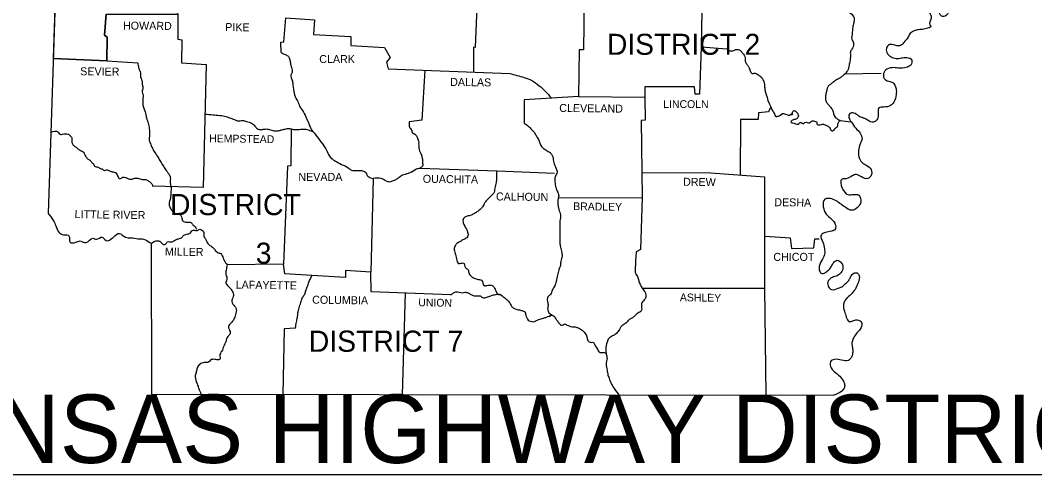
# Model space of a CAD drawing. Extents: x -13171 to 18763, y -8840 to 11152.
# Drawn here: x 10714 to 16044, y 4654 to 7050 of the extents above; entities that cross this region are included whole.
import ezdxf

# ---------------------------------------------------------------- set-up
doc = ezdxf.new("R2010")
doc.units = 0
for name, color, linetype in [('Level 1', 7, 'Continuous'), ('Level 2', 7, 'Continuous'), ('Level 3', 7, 'Continuous'), ('Level 48', 7, 'Continuous')]:
    doc.layers.add(name, color=color, linetype=linetype)

msp = doc.modelspace()

# ---------------------------------------------------------------- linework, layer by layer
at = {"layer": 'Level 1'}
for p, q in [((15042.6, 6768.2), (15238.2, 6771.2)), ((9238.8, 4659.5), (17153.7, 4659.5))]:
    msp.add_line(p, q, dxfattribs=at)
for points in [[(10745.4, 10313), (10947.9, 8686.9), (10859.9, 6032.5)], [(13678.7, 7289.7), (13672.8, 6894.4), (13650.3, 6893.5), (13647.3, 6647.9)], [(14299.1, 7294.1), (14291.1, 6910.1), (14427.1, 6899.3)], [(13115.1, 7162.5), (13103.4, 6906.2), (13094.5, 6909.1), (13095.5, 6776)], [(11165.1, 7082.3), (11156.3, 6970.8), (11170, 6961), (11169, 6835.7), (10887, 6848.1)], [(11541.8, 7081.3), (11541.8, 6951.2), (11563.3, 6947.3), (11561.4, 6825.9), (11690.5, 6816.2), (11674.9, 6169.4), (11408.8, 6176.3)], [(12084.8, 6880.7), (12082.9, 6934.5), (12098.5, 6935.5), (12108.3, 7061.7), (12259, 7052), (12255.1, 6974.7), (12449.8, 6963.9), (12450.8, 6916.9), (12626.9, 6906.2), (12657.2, 6853.3), (12638.6, 6829.9), (12647.4, 6793.7), (13285.3, 6770.2)], [(14291.1, 6910.1), (14282.3, 6661.6), (14259.8, 6661.6), (14255.9, 6699.7), (13995.7, 6699.7), (13995.7, 6644.9)], [(11169, 6835.7), (11331.5, 6825.9)], [(12839.9, 6786.6), (12824.5, 6523.6), (12757, 6515.8)], [(13506.5, 6639.1), (13361.7, 6630.3), (13360.7, 6508)], [(13647.3, 6647.9), (13504.5, 6639.1)], [(13647.3, 6647.9), (13995.7, 6645.9)], [(13995.7, 6645.9), (13996.6, 6523.6), (13976.1, 6522.6), (13982, 6116.6)], [(14657.1, 6594.1), (14645.3, 6567.6), (14593.5, 6562.8), (14590.5, 6527.5), (14497.6, 6527.5), (14496.6, 6235)], [(14766.6, 6551), (14769.6, 6553.9), (14772.5, 6556.9), (14772.5, 6556.9)], [(12136.7, 6478.6), (12134.7, 6283.9), (12117.1, 6282), (12097.5, 5766.3)], [(12814.7, 6272.2), (13219.8, 6257.5), (13520.2, 6245.8)], [(13979, 6249.7), (14342, 6246.7), (14623.8, 6225.2)], [(12568.2, 6217.4), (12555.4, 5724.3), (12423.4, 5733.1), (12422.4, 5696.9), (12246.3, 5707.6)], [(14623.8, 6225.2), (14623.8, 5640.1), (14631.6, 5077.5)], [(13539.7, 6115.6), (13982, 6116.6)], [(13982, 6116.6), (13972.2, 5844.6), (13950.7, 5830.9)], [(11400.9, 5874.9), (11402.9, 5083.4), (14988.7, 5077.5)], [(14628.7, 5913.1), (14759.8, 5905.3), (14765.7, 5848.5), (14884.1, 5852.4), (14888.9, 5900.4), (14911.4, 5900.4)], [(12246.3, 5707.6), (12104.4, 5715.5), (12097.5, 5766.3), (11801.1, 5763.4)], [(12975.2, 5604.9), (12557.4, 5620.5), (12555.3, 5724.3)], [(12735.5, 5613.9), (12720, 5081.2)], [(13981.6, 5641.1), (14623.8, 5641.1)], [(12160.2, 5430.7), (12099.5, 5426.8), (12092.7, 5082.4)]]:
    msp.add_lwpolyline(points, dxfattribs=at)
for points in [[(15812.6, 7720.2), (15790.1, 7691.8), (15756.8, 7709.4), (15756.8, 7732.9), (15761.7, 7757.4), (15749.9, 7773), (15729.4, 7766.2), (15729.4, 7735.9), (15727.4, 7706.5), (15721.6, 7664.4), (15735.3, 7651.7), (15766.6, 7647.8), (15789.1, 7641.9), (15802.8, 7619.4), (15801.8, 7592), (15791, 7565.6), (15775.4, 7544.1), (15750.9, 7536.3), (15731.4, 7549), (15723.5, 7574.4), (15714.7, 7596.9), (15698.1, 7613.6), (15680.5, 7595), (15676.6, 7560.7), (15677.5, 7531.4), (15677.5, 7491.3), (15703, 7464.8), (15718.6, 7434.5), (15713.7, 7407.1), (15695.2, 7374.8), (15687.3, 7346.5), (15679.5, 7308.3), (15680.5, 7266.2), (15673.6, 7225.1), (15659.9, 7197.7), (15634.5, 7175.2), (15617.9, 7160.6), (15604.2, 7145.9), (15597.3, 7116.5), (15592.4, 7096), (15573.8, 7071.5), (15559.2, 7069.6), (15547.4, 7079.4), (15543.5, 7096), (15543.5, 7112.6), (15535.7, 7129.3), (15511.2, 7136.1), (15491.6, 7135.1), (15482.8, 7121.4), (15495.6, 7083.3), (15500.4, 7058.8), (15493.6, 7025.5), (15497.5, 7021.6), (15462.3, 7003), (15433.9, 7000.1), (15410.4, 6993.3), (15387.9, 6978.6), (15377.2, 6957.1), (15361.5, 6939.4), (15347.8, 6922.8), (15329.2, 6915), (15308.7, 6918.9), (15281.3, 6921.8), (15265.6, 6902.3), (15270.5, 6873.9), (15289.1, 6857.3), (15316.5, 6849.4), (15344.9, 6851.4), (15372.3, 6854.3), (15397.7, 6840.6), (15392.8, 6814.2), (15368.4, 6801.5), (15332.2, 6797.6), (15302.8, 6800.5), (15267.6, 6792.7), (15250, 6770.2), (15259.8, 6735.9), (15297.9, 6722.2), (15315.5, 6689.9), (15316.5, 6659.6), (15303.8, 6619.5), (15286.2, 6600.9), (15251.9, 6593.1), (15225.5, 6588.2), (15221.6, 6543.2), (15209.9, 6520.7), (15189.3, 6513.8), (15160, 6528.5), (15142.4, 6535.4), (15120.8, 6545.1), (15093.4, 6561.8), (15072.9, 6558.8), (15078.8, 6515.8), (15080.7, 6513.8), (15104.2, 6481.5), (15127.7, 6456.1), (15138.4, 6425.8)], [(14798.9, 7405.2), (14801.9, 7365), (14825.3, 7359.2), (14835.1, 7348.4), (14840, 7325.9), (14856.7, 7316.1), (14879.2, 7302.4), (14892.9, 7292.6), (14902.6, 7277), (14908.5, 7251.6), (14924.2, 7234.9), (14945.7, 7227.1), (14961.3, 7208.5), (14971.1, 7182.1), (14986.8, 7170.3), (15002.4, 7149.8), (15010.3, 7141), (15024, 7117.5), (15037.7, 7105.8), (15047.4, 7098.9), (15063.1, 7094), (15082.7, 7081.3), (15095.4, 7061.7), (15095.4, 7047.1), (15090.5, 7024.6), (15086.6, 7001.1), (15084.6, 6974.7), (15082.7, 6951.2), (15091.5, 6931.6), (15086.6, 6902.3), (15076.8, 6886.6), (15075.8, 6865.1), (15072.9, 6832.8), (15069, 6814.2), (15060.2, 6783.9), (15047.4, 6768.2)], [(12084.8, 6880.7), (12100.5, 6871), (12119.1, 6862.1), (12128.9, 6847.5), (12132.8, 6825), (12139.6, 6800.5), (12141.6, 6775.1), (12135.7, 6761.4), (12143.5, 6730.1), (12146.5, 6708.5), (12149.4, 6683.1), (12157.2, 6648.9), (12170, 6625.4), (12181.7, 6597), (12201.3, 6566.7), (12217.9, 6533.4), (12225.7, 6515.8), (12240.4, 6479.6), (12259, 6455.1), (12288.3, 6418), (12314.8, 6379.8), (12329.4, 6351.4), (12351.9, 6320.1), (12377.4, 6304.5), (12409.7, 6287.8), (12430.2, 6278), (12453.7, 6261.4), (12484, 6259.4), (12506.5, 6259.4), (12527.1, 6250.6), (12536.9, 6233), (12554.5, 6221.3), (12568.2, 6217.4)], [(14427.1, 6899.3), (14441.8, 6889.5), (14462.4, 6890.5), (14476.1, 6896.4), (14486.8, 6895.4), (14501.5, 6886.6), (14511.3, 6874.9), (14518.1, 6866.1), (14523, 6852.4), (14523, 6839.6), (14527.9, 6822), (14533.8, 6815.2), (14541.6, 6802.5), (14546.5, 6790.7), (14549.4, 6782.9), (14560.2, 6770.2), (14570, 6771.2), (14578.8, 6770.2), (14590.5, 6763.3), (14608.1, 6749.6), (14611.1, 6745.7), (14622.8, 6720.3), (14624.8, 6704.6), (14626.7, 6684.1), (14630.6, 6664.5), (14638.5, 6643), (14642.4, 6628.3), (14651.2, 6607.8), (14657.1, 6594.1), (14664.9, 6576.5), (14676.6, 6556.9), (14681.5, 6545.1), (14698.2, 6546.1), (14709.9, 6551), (14718.7, 6558.8), (14729.5, 6557.9), (14741.2, 6553.9), (14756.9, 6551), (14766.6, 6556.9), (14771.5, 6560.8), (14772.5, 6569.6), (14781.3, 6574.5), (14791.1, 6567.6), (14801.9, 6552), (14801.9, 6542.2), (14798, 6536.3), (14785.2, 6528.5), (14767.6, 6522.6), (14762.7, 6515.8), (14779.4, 6508), (14805.8, 6506), (14812.6, 6511.9), (14830.2, 6507), (14837.1, 6511.9), (14860.6, 6510.9), (14871.3, 6518.7), (14892.9, 6517.7), (14899.7, 6512.9), (14899.7, 6504.1), (14917.3, 6500.1), (14930, 6503.1), (14946.7, 6498.2), (14961.3, 6490.4), (14969.2, 6479.6), (14979, 6467.8), (14987.8, 6470.8), (14994.6, 6479.6), (15009.3, 6495.2), (15009.3, 6505), (15013.2, 6511.9), (15019.6, 6524.7)], [(11331.5, 6825.9), (11336.3, 6796.6), (11345.2, 6771.2), (11346.1, 6751.6), (11354.9, 6722.2), (11354.9, 6711.5), (11357.9, 6689.9), (11354, 6678.2), (11358.9, 6654.7), (11357.9, 6637.1), (11357.9, 6622.4), (11358.9, 6598), (11366.7, 6576.5), (11374.5, 6544.2), (11379.4, 6527.5), (11387.2, 6502.1), (11392.1, 6470.8), (11393.1, 6447.3), (11391.1, 6425.8), (11397, 6401.3), (11407.8, 6376.9), (11421.5, 6353.4), (11438.1, 6327), (11449.8, 6306.4), (11464.5, 6283.9), (11476.3, 6265.3), (11493.9, 6241.8), (11501.7, 6222.3), (11501.7, 6194.9), (11505.6, 6169.4), (11504.6, 6141.1), (11502.7, 6115.6), (11495.8, 6080.4), (11500.7, 6063.8), (11519.3, 6039.3), (11531.1, 6032.5), (11551.6, 6028.5), (11561.4, 6014.8), (11567.3, 5994.3), (11587.8, 5987.5), (11610.3, 5985.5), (11621.1, 5973.8), (11635.7, 5958.1), (11640.6, 5950.3)], [(13285.3, 6770.2), (13361.7, 6748.7), (13400.8, 6734), (13439.9, 6705.6), (13472.2, 6677.2), (13504.5, 6639.1)], [(15047.4, 6768.2), (15040.9, 6762.1), (15034.2, 6756.3), (15027.3, 6750.8), (15020, 6745.7), (15015.7, 6743.2), (15011.2, 6740.9), (15006.7, 6738.6), (15002.4, 6735.9), (14983.8, 6722.2), (14972.6, 6713.9), (14967, 6709.8), (14961.3, 6705.6), (14956.6, 6700), (14953.9, 6692.9), (14952.2, 6685), (14951.4, 6681.1), (14950.6, 6677.2), (14949.4, 6672.4), (14948.2, 6667.5), (14946.3, 6657.6), (14945, 6647.8), (14944.7, 6643), (14944.7, 6638.1), (14945.3, 6632), (14946.8, 6626), (14949.2, 6620.2), (14950.8, 6617.4), (14952.5, 6614.6), (14956.8, 6609.1), (14961.3, 6604.1), (14965.8, 6599.2), (14970.2, 6594.1), (14976.2, 6585.9), (14981.9, 6577.4), (14983.6, 6574.1), (14984.8, 6570.5), (14986.2, 6562.9), (14987.7, 6555.2), (14988.9, 6551.5), (14989.7, 6549.8), (14990.7, 6548.1), (14992.8, 6544.9), (15000.2, 6536.5), (15005.9, 6531.7), (15010.6, 6528.5), (15012.2, 6527.5), (15017.3, 6524.9), (15022.5, 6522.8)], [(11684.2, 6556.2), (11725.8, 6553), (11760, 6549.1), (11786.4, 6546.1), (11813.8, 6536.3), (11838.3, 6527.5), (11853.9, 6520.7), (11880.3, 6522.6), (11902.8, 6517.7), (11928.3, 6508.9), (11946.9, 6492.3), (11958.6, 6479.6), (11981.1, 6474.7), (11999.7, 6477.6), (12022.2, 6475.7), (12047.7, 6467.8), (12068.2, 6468.8), (12084.8, 6472.7), (12104.4, 6477.6), (12128.9, 6479.6), (12147.4, 6475.7), (12171.9, 6474.7), (12200.3, 6477.6), (12253.6, 6462.8)], [(12757, 6515.8), (12757, 6497.2), (12763.8, 6479.6), (12770.7, 6471.8), (12773.6, 6459), (12782.4, 6453.2), (12795.2, 6441.4), (12802, 6424.8), (12806.9, 6414), (12806.9, 6400.3), (12807.9, 6386.6), (12809.8, 6370), (12821.6, 6340.7), (12824.5, 6328.9), (12826.5, 6319.1), (12827.4, 6302.5), (12827.4, 6282.9), (12814.7, 6272.2)], [(13360.7, 6508), (13383.2, 6493.3), (13401.8, 6473.7), (13415.5, 6459), (13424.3, 6442.4), (13436, 6422.8), (13452.6, 6385.7), (13467.3, 6372.9), (13487.9, 6360.2), (13500.6, 6351.4), (13513.3, 6323), (13519.2, 6294.7), (13529.9, 6269.2), (13534.8, 6249.7), (13526, 6230.1), (13524.1, 6191), (13529.9, 6164.5), (13537.8, 6145), (13542.7, 6122.5), (13539.7, 6115.6)], [(10873.8, 6460.3), (10911.7, 6462), (10926.4, 6449.3), (10935.2, 6450.2), (10950.9, 6452.2), (10965.5, 6451.2), (10976.3, 6442.4), (10985.1, 6426.8), (10984.1, 6412.1), (10985.1, 6406.2), (10991.9, 6393.5), (11003.7, 6383.7), (11016.4, 6373.9), (11028.2, 6366.1), (11047.7, 6353.4), (11049.7, 6349.5), (11057.5, 6333.8), (11067.3, 6321.1), (11079, 6313.3), (11091.7, 6299.6), (11097.6, 6293.7), (11107.4, 6280), (11118.2, 6279), (11132.8, 6270.2), (11143.6, 6267.3), (11155.3, 6259.4), (11167.1, 6263.4), (11181.8, 6257.5), (11201.3, 6251.6), (11212.1, 6249.7), (11224.8, 6231.1), (11237.5, 6215.4), (11253.2, 6224.2), (11282.5, 6215.4), (11301.1, 6214.4), (11317.8, 6219.3), (11330.5, 6218.4), (11354, 6212.5), (11368.6, 6212.5), (11384.3, 6206.6), (11399, 6194.9), (11408.8, 6182.2), (11408.8, 6176.3)], [(15138.4, 6425.8), (15128.7, 6403.3), (15117.9, 6364.1), (15120.8, 6330.9), (15135.5, 6302.5), (15159, 6286.8), (15184.4, 6264.3), (15182.5, 6230.1), (15167.8, 6217.4), (15133.5, 6226.2), (15107.1, 6237.9), (15084.6, 6231.1), (15054.3, 6216.4), (15031.8, 6213.5), (15032.8, 6166.5), (15063.1, 6133.2), (15089.5, 6133.2), (15119.8, 6129.3), (15130.6, 6094.1), (15113, 6064.7), (15083.6, 6050.1), (15046.5, 6067.7), (15020, 6086.3), (14993.6, 6103.9), (14960.4, 6112.7), (14941.8, 6108.8), (14933, 6067.7), (14948.6, 6030.5), (14974.1, 6005.1), (14997.5, 5971.8), (14993.6, 5947.3), (14976, 5940.5), (14944.7, 5933.6), (14926.1, 5923.9), (14921.2, 5916), (14931, 5882.8), (14939.8, 5846.6), (14939.8, 5819.2), (14929.1, 5793.7), (14912.4, 5754.6), (14914.4, 5729.2), (14926.1, 5717.4), (14940.8, 5721.3), (14960.4, 5735), (14973.1, 5750.7), (14983.8, 5770.2), (15004.4, 5786.9), (15029.8, 5772.2), (15035.7, 5741.9), (15021, 5715.5), (15000.5, 5703.7), (14975, 5693.9), (14956.5, 5672.4), (14961.3, 5647), (14976, 5633.3), (15012.2, 5640.1), (15036.7, 5650.9), (15050.4, 5664.6), (15067, 5681.2), (15075.8, 5697.8), (15088.5, 5715.5), (15111, 5720.3), (15121.8, 5705.7), (15117.9, 5672.4), (15104.2, 5641.1), (15085.6, 5614.7), (15065.1, 5596.1), (15039.6, 5556), (15044.5, 5518.8), (15054.3, 5488.5), (15068, 5465), (15091.5, 5469.9), (15117.9, 5472.8), (15133.5, 5460.1), (15131.6, 5432.7), (15112, 5406.3), (15093.4, 5380.8), (15083.6, 5345.6), (15087.6, 5321.2), (15087.6, 5298.7), (15079.7, 5274.2), (15066, 5260.5), (15029.8, 5261.5), (14991.7, 5265.4), (14971.1, 5253.6), (14975, 5220.4), (14997.5, 5195.9), (15013.2, 5183.2), (15035.7, 5155.8), (15045.5, 5133.3), (15042.6, 5113.7), (15028.9, 5097.1), (14988.7, 5077.5)], [(12796.1, 6268.3), (12770.7, 6251.6), (12751.1, 6243.8), (12736.4, 6238.9), (12722.8, 6235), (12705.1, 6223.2), (12691.4, 6213.5), (12672.9, 6204.7), (12655.2, 6198.8), (12633.7, 6205.6), (12622, 6212.5), (12609.3, 6217.4), (12568.2, 6217.4)], [(12770.7, 6251.6), (12796.1, 6268.3), (12814.7, 6272.2)], [(13216.4, 6257.8), (13213.9, 6196.8), (13207.1, 6166.5), (13200.2, 6139.1), (13185.5, 6123.5), (13169.9, 6107.8), (13155.2, 6090.2), (13142.5, 6068.7), (13129.8, 6055), (13113.1, 6041.3), (13096.5, 6031.5), (13077.9, 6022.7), (13057.4, 6017.8), (13042.7, 6007), (13041.7, 5983.5), (13058.3, 5950.3), (13064.2, 5934.6), (13066.2, 5916), (13059.3, 5905.3), (13043.7, 5896.5), (13025.1, 5885.7), (13008.4, 5875.9), (12996.7, 5859.3), (12994.7, 5836.8), (13002.6, 5810.4), (13005.5, 5794.7), (13018.2, 5770.2), (13028, 5771.2), (13045.6, 5770.2), (13047.6, 5765.4), (13048.6, 5760.5), (13052.5, 5747.7), (13067.1, 5737), (13069.1, 5727.2), (13077.9, 5708.6), (13092.6, 5695.9), (13103.4, 5692), (13125.9, 5685.1), (13137.6, 5682.2), (13150.3, 5653.8), (13166, 5654.8), (13177.7, 5656.8), (13197.3, 5651.9), (13206.1, 5640.1), (13214.9, 5620.5), (13226.6, 5606.9), (13234.5, 5606.9)], [(13539.7, 6115.6), (13543.6, 6055), (13552.4, 6025.6), (13549.5, 5994.3), (13548.5, 5964), (13548.5, 5936.6), (13548.5, 5910.2), (13548.5, 5882.8), (13550.5, 5863.2), (13557.3, 5834.8), (13560.3, 5808.4), (13554.4, 5783), (13551.5, 5759.5), (13543.6, 5736), (13536.8, 5709.6), (13529, 5675.3), (13522.1, 5652.8), (13508.4, 5629.4), (13499.6, 5607.8), (13485.9, 5594.1), (13484, 5570.7), (13486.9, 5549.1), (13484.9, 5529.6), (13491.8, 5511), (13509.4, 5498.2)], [(10859.9, 6032.5), (10888.2, 5995.3), (10900, 5968.9), (10916.6, 5934.6), (10941.1, 5920.9), (10969.4, 5916), (10975.3, 5882.8), (11004.7, 5881.8), (11028.2, 5888.6), (11060.4, 5879.8), (11094.7, 5903.3), (11114.2, 5897.4), (11142.6, 5909.2), (11164.1, 5891.6), (11201.3, 5907.2), (11234.6, 5928.7), (11265.9, 5908.2), (11296.2, 5905.3), (11332.4, 5900.4), (11360.8, 5898.4), (11386.2, 5885.7), (11404.8, 5873), (11400.9, 5874.9)], [(11400.9, 5874.9), (11435.2, 5889.6), (11449.8, 5884.7), (11462.6, 5872), (11477.2, 5872), (11485.1, 5883.7), (11499.7, 5884.7), (11511.5, 5883.7), (11524.2, 5891.6), (11535, 5896.5), (11549.6, 5901.4), (11560.4, 5905.3), (11570.2, 5916), (11587.8, 5924.8), (11608.3, 5931.7), (11614.2, 5941.5), (11624, 5945.4), (11643.6, 5944.4), (11656.3, 5950.3), (11667, 5945.4), (11676.8, 5938.5), (11678.8, 5913.1), (11686.6, 5899.4), (11698.4, 5874.9), (11715, 5862.2), (11730.6, 5849.5), (11736.5, 5841.7), (11753.1, 5827), (11767.8, 5822.1), (11774.7, 5811.3), (11785.4, 5785.9), (11801.1, 5763.4)], [(13950.7, 5830.9), (13947.7, 5800.6), (13946.7, 5772.2), (13944.8, 5744.8), (13944.8, 5724.3), (13956.5, 5701.8), (13963.4, 5680.2), (13970.2, 5661.6), (13983.9, 5637.2), (13996.6, 5618.6), (14000.6, 5592.2), (13992.7, 5578.5), (13978, 5557.9), (13977.1, 5520.8), (13959.5, 5509), (13937, 5489.4), (13924.2, 5480.6), (13910.5, 5471.8), (13895.9, 5456.2), (13874.3, 5441.5), (13858.7, 5417), (13841.1, 5398.5), (13826.4, 5388.7), (13805.8, 5375.9), (13797, 5356.4), (13790.2, 5320.2), (13793.1, 5293.8), (13797, 5270.3), (13792.1, 5240.9), (13797, 5208.6), (13801.9, 5183.2), (13809.8, 5160.7), (13820.5, 5135.3), (13834.2, 5111.8), (13863.6, 5075.6)], [(11801.1, 5763.4), (11795.2, 5735), (11794.2, 5712.5), (11799.1, 5686.1), (11794.2, 5673.4), (11802.1, 5654.8), (11816.7, 5640.1), (11827.5, 5624.5), (11834.4, 5602), (11825.6, 5576.5), (11835.3, 5550.1), (11844.1, 5540.3), (11849, 5524.7), (11842.2, 5494.3), (11833.4, 5471.8), (11813.8, 5449.3), (11807.9, 5438.6), (11810.9, 5423.9), (11815.8, 5400.4), (11810.9, 5393.6), (11798.2, 5376.9), (11794.2, 5358.3), (11785.4, 5342.7), (11775.7, 5314.3), (11762.9, 5290.8), (11761, 5264.4), (11741.4, 5264.4), (11718.9, 5264.4), (11698.4, 5249.7), (11679.8, 5248.8), (11657.3, 5239.9), (11643.6, 5221.4), (11638.7, 5200.8), (11632.8, 5181.2), (11638.7, 5148), (11647.5, 5124.5), (11654.3, 5105.9), (11666.1, 5075.6)], [(12160.2, 5430.7), (12165.1, 5462), (12170, 5486.5), (12172.9, 5510), (12178.8, 5536.4), (12187.6, 5564.8), (12195.4, 5588.3), (12206.2, 5604.9), (12213, 5624.5), (12221.8, 5647.9), (12230.6, 5672.4), (12246.3, 5707.6)], [(12975.2, 5604.9), (12990.8, 5615.7), (13005.5, 5621.5), (13020.2, 5618.6), (13035.8, 5616.6), (13049.5, 5618.6), (13067.1, 5615.7), (13081.8, 5606.9), (13098.5, 5600), (13115.1, 5600), (13129.8, 5600), (13142.5, 5591.2), (13166, 5592.2), (13185.5, 5600), (13205.1, 5605.9), (13231.5, 5608.8), (13255, 5592.2), (13271.6, 5578.5), (13285.3, 5562.8), (13295.1, 5545.2), (13305.9, 5535.4), (13323.5, 5528.6), (13337.2, 5525.6), (13353.8, 5520.8), (13362.6, 5516.8), (13370.5, 5498.2), (13383.2, 5472.8), (13407.6, 5464), (13438, 5475.7), (13462.4, 5482.6), (13480, 5488.5), (13490.8, 5492.4), (13500.6, 5493.4), (13497.6, 5495.3), (13509.4, 5498.2), (13520.2, 5490.4), (13527, 5479.7), (13538.7, 5464), (13549.5, 5450.3), (13560.3, 5445.4), (13571, 5451.3), (13585.7, 5446.4), (13598.4, 5441.5), (13613.1, 5437.6), (13625.8, 5436.6), (13642.5, 5432.7), (13655.2, 5425.8), (13666.9, 5419), (13678.7, 5406.3), (13690.4, 5386.7), (13694.3, 5371.1), (13708, 5355.4), (13720.7, 5355.4), (13739.3, 5330), (13746.2, 5320.2), (13760.8, 5302.6), (13771.6, 5302.6), (13792.1, 5298.7)]]:
    msp.add_spline(points, degree=3, dxfattribs=at)
at = {"layer": 'Level 3'}
msp.add_line((15022.5, 6522.8), (15077.8, 6515.8), dxfattribs=at)
at = {"layer": 'Level 48'}
for p, q in [((10913.7, 7654.7), (10886.9, 6848.1)), ((10887, 6848.1), (11169, 6835.7))]:
    msp.add_line(p, q, dxfattribs=at)
for points in [[(11169, 6835.7), (11170, 6961), (11156.3, 6970.8), (11165.1, 7082.3), (11541.8, 7081.3), (11552.4, 7556.8)], [(10886.9, 6848.1), (10887, 6848.1)]]:
    msp.add_lwpolyline(points, dxfattribs=at)

# ---------------------------------------------------------------- texts
at = {"layer": 'Level 2'}
for s, height, rotation, p in [('HOWARD', 42.07, 359.5145, (11253.2, 7001.1)), ('PIKE', 42.06, 359.0452, (11790.3, 6993.3)), ('SEVIER', 42.07, 359.4271, (11028.2, 6760.4)), ('DALLAS', 42.06, 359.2462, (12972.2, 6704.6)), ('CLEVELAND', 42.07, 359.3377, (13545.6, 6567.6)), ('HEMPSTEAD', 41.08, 359.1885, (11706.2, 6408.2)), ('OUACHITA', 42.07, 359.2043, (12828.4, 6194.9)), ('DREW', 42.06, 359.2258, (14196.2, 6179.2)), ('CALHOUN', 42.07, 359.3634, (13212.9, 6101.9)), ('BRADLEY', 41.08, 359.1449, (13619, 6051)), ('DESHA', 42.06, 359.3704, (14675.7, 6071.6)), ('LITTLE RIVER', 42.073, 359.1697, (10998.8, 6009)), ('MILLER', 42.06, 359.1319, (11473.3, 5812.3)), ('LAFAYETTE', 42.06, 359.1839, (11845.1, 5638.2)), ('COLUMBIA', 42.06, 359.2125, (12247.2, 5558.9)), ('ASHLEY', 41.09, 359.2361, (14179.6, 5571.6)), ('UNION', 41.09, 358.9584, (12804.9, 5545.2))]:
    msp.add_text(s, height=height, rotation=rotation, dxfattribs=at).set_placement(p)
for s, height, p in [('CLARK', 42.07, (12284.6, 6824.7)), ('LINCOLN', 41.09, (14092.5, 6588.2)), ('NEVADA', 42.07, (12174.8, 6204.7)), ('CHICOT', 42.07, (14670.8, 5783.9)), ('ARKANSAS HIGHWAY DISTRICTS 4, 8 & 9', 360, (9262.7, 4720.5))]:
    msp.add_text(s, height=height, dxfattribs=at).set_placement(p)
at = {"layer": 'Level 3'}
for s, height, p in [('DISTRICT 2', 110.56, (13797, 6868)), ('DISTRICT', 111.54, (11500.2, 6024.5)), ('3', 110.6, (11951.3, 5769.2)), ('DISTRICT 7', 111.54, (12229.6, 5305.5))]:
    msp.add_text(s, height=height, dxfattribs=at).set_placement(p)

doc.saveas('drawing.dxf')
